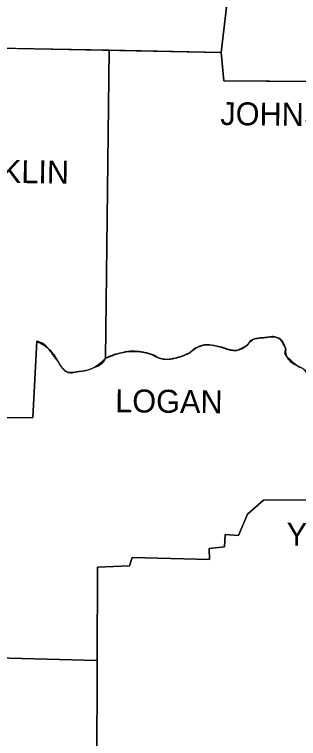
# Model space of a CAD drawing. Extents: x -28335 to 1228743, y -22428 to 152440.
# Drawn here: x 26423 to 27629, y 11936 to 15008 of the extents above; entities that cross this region are included whole.
import ezdxf

# ---------------------------------------------------------------- set-up
doc = ezdxf.new("R2010")
doc.units = 0
doc.layers.add('R_Draft', color=7, linetype='Continuous')
doc.layers.add('R_No Plot', color=7, linetype='Continuous')

msp = doc.modelspace()

# ---------------------------------------------------------------- linework, layer by layer
at = {"layer": 'R_Draft'}
for points in [[(24439, 16052.3), (24870.9, 16049.9), (24882.2, 16199.5), (25038.5, 16199.5), (25052.1, 16441.8), (25935.6, 16410.1), (25962.7, 16478.1), (26327.5, 16480.3), (26144, 15954.8), (26107.7, 15114.4), (26080.5, 15112.1), (26066.9, 14858.4), (26200.6, 14847.1), (26221, 14867.5), (27301.5, 14847.1), (27312.9, 14727)], [(27430.3, 16079.9), (27439.7, 15952.5), (27543.9, 15945.7), (27516.7, 15565.2), (27469.2, 15567.5), (27460.1, 15506.3), (27405.7, 15506.3), (27403.5, 15402.1), (27369.5, 15399.8), (27358.2, 15266.2), (27308.3, 15259.4), (27301.5, 15055.5), (27324.2, 15039.6), (27301.5, 14847.1)], [(27312.9, 14727), (29827.4, 14706.7), (29838.7, 14944.5), (30429, 14937.6)], [(26825.8, 14856.2), (26810, 13549.1)], [(26517.7, 13621.6), (26501.9, 13297.7), (26207.4, 13295.4), (26191.5, 13000.9), (25899.3, 13007.7), (25890.3, 12704.2), (25584.4, 12701.9), (25575.4, 12398.4), (25767.9, 12387), (25761.1, 12294.2), (26774.6, 12266.1)], [(28006, 13275), (27997, 12948.8), (27480.5, 12946.6), (27412.5, 12887.7), (27374, 12797.1), (27317.4, 12801.6), (27315.1, 12749.5), (27249.4, 12742.7), (27251.7, 12695.1), (26923.2, 12704.2), (26911.9, 12667.9), (26776, 12663.4), (26774.6, 12266.1)], [(26774.6, 12266.1), (26771.5, 11338.2), (26658.2, 11336), (26667.3, 11268), (26558.5, 11270.3), (26556.3, 11220.4), (26449.8, 11220.4), (26452.1, 11184.2), (26293.5, 11179.7), (26291.2, 11041.5), (26137.2, 11055.1), (26112.3, 9940.6), (25240.1, 9942.8), (25219.7, 9684.6), (25251.4, 9662), (25249.2, 9372), (24596, 9400.7)]]:
    msp.add_lwpolyline(points, dxfattribs=at)
for points in [[(26810, 13549.1), (26884.7, 13574), (26939.1, 13578.6), (26993.5, 13569.5), (27050.1, 13546.9), (27111.3, 13551.4), (27156.6, 13567.2), (27201.9, 13596.7), (27251.7, 13605.7), (27299.3, 13596.7), (27349.1, 13583.1), (27403.5, 13599), (27435.2, 13628.4), (27489.6, 13637.5), (27537.1, 13637.5), (27571.1, 13599), (27577.9, 13558.2), (27620.9, 13519.7), (27659.5, 13494.8), (27670.8, 13447.2), (27691.2, 13413.2), (27711.6, 13390.6), (27741, 13377), (27790.8, 13381.5), (27867.9, 13365.6), (27917.7, 13354.3), (27963, 13315.8), (28006, 13275)], [(26517.7, 13621.6), (26567.6, 13589.9), (26606.1, 13537.8), (26640.1, 13494.8), (26696.7, 13492.5), (26742, 13501.5), (26810, 13549.1)]]:
    msp.add_spline(points, degree=3, dxfattribs=at)
at = {"layer": 'R_No Plot'}
for p, q in [((26810, 13549.1), (26825.8, 14856.1)), ((26825.8, 14856.1), (26810, 13549.1)), ((26825.8, 14856.2), (26825.8, 14856.1)), ((26825.8, 14856.1), (27301.5, 14847.1)), ((27301.5, 14847.1), (26825.8, 14856.1)), ((27301.5, 14847.1), (27312.9, 14727)), ((27312.9, 14727), (27301.5, 14847.1)), ((27312.9, 14727), (28932.4, 14713.9)), ((28369.2, 14718.5), (27312.9, 14727)), ((27249.6, 13606), (27251.7, 13605.7)), ((27577.9, 13558.2), (27615.6, 13523.8)), ((27041.9, 13548.9), (27050.1, 13546.9)), ((27317.4, 12801.6), (27315.1, 12749.5)), ((27315.1, 12749.5), (27249.4, 12742.7)), ((26923.2, 12704.2), (26911.9, 12667.9)), ((26776, 12663.4), (26774.6, 12266.1)), ((26911.9, 12667.9), (26776, 12663.4)), ((26774.6, 12266.1), (26771.5, 11338.2))]:
    msp.add_line(p, q, dxfattribs=at)
for points in [[(26327.5, 16480.3), (26144, 15954.8), (26107.7, 15114.4), (26080.5, 15112.1), (26067.3, 14865.5), (26066.9, 14858.4), (26200.6, 14847.1), (26221, 14867.5), (26825.8, 14856.1)], [(27430.3, 16079.9), (27439.7, 15952.5), (27543.9, 15945.7), (27516.7, 15565.2), (27469.2, 15567.5), (27460.1, 15506.3), (27405.7, 15506.3), (27403.5, 15402.1), (27369.5, 15399.8), (27358.2, 15266.2), (27308.3, 15259.4), (27301.5, 15055.5), (27324.2, 15039.6), (27301.5, 14847.1)], [(27301.5, 14847.1), (27324.2, 15039.6), (27301.5, 15055.5), (27308.3, 15259.4)], [(26825.8, 14856.1), (26825.8, 14856.1), (26266.3, 14866.6)], [(26825.8, 14856.1), (26825.8, 14856.2)], [(25897.4, 12943.2), (25899.3, 13007.7), (26191.5, 13000.9), (26207.4, 13295.4), (26501.9, 13297.7), (26517.7, 13621.6)], [(26517.7, 13621.6), (26501.9, 13297.7), (26207.4, 13295.4)], [(26774.6, 12266.1), (26776, 12663.4), (26911.9, 12667.9), (26923.2, 12704.2), (27251.7, 12695.1), (27249.4, 12742.7), (27315.1, 12749.5), (27317.4, 12801.6), (27374, 12797.1), (27412.5, 12887.7), (27480.5, 12946.6), (27997, 12948.8), (28006, 13275)], [(28006, 13275), (27997, 12948.8), (27480.5, 12946.6), (27412.5, 12887.7)], [(25897.4, 12943.2), (25890.3, 12704.2), (25584.4, 12701.9), (25575.4, 12398.4), (25767.9, 12387), (25761.1, 12294.2), (26774.6, 12266.1)], [(27412.5, 12887.7), (27374, 12797.1), (27317.4, 12801.6)], [(27249.4, 12742.7), (27251.7, 12695.1), (26923.2, 12704.2)], [(26774.6, 12266.1), (25761.1, 12294.2), (25767.9, 12387), (25575.4, 12398.4), (25580.9, 12584.5)], [(26137.2, 11055.1), (26291.2, 11041.5), (26293.5, 11179.7), (26452.1, 11184.2), (26449.8, 11220.4), (26556.3, 11220.4), (26558.5, 11270.3), (26667.3, 11268), (26658.2, 11336), (26771.5, 11338.2), (26774.6, 12266.1)]]:
    msp.add_lwpolyline(points, dxfattribs=at)
for points, degree in [([(28006, 13275), (27992.2, 13289.2), (27977.5, 13302.3), (27963, 13315.8), (27948.5, 13329.3), (27936.6, 13347.1), (27917.7, 13354.3), (27901.5, 13360.5), (27884.5, 13362.1), (27867.9, 13365.6), (27842.2, 13371.1), (27816.5, 13376.5), (27790.8, 13381.5), (27774.5, 13384.7), (27757.5, 13374.4), (27741, 13377), (27730.3, 13378.6), (27720.4, 13383.2), (27711.6, 13390.6), (27703.2, 13397.5), (27697.2, 13404.8), (27691.2, 13413.2), (27683.3, 13424.1), (27676.8, 13435.5), (27670.8, 13447.2), (27663.3, 13461.6), (27670.7, 13482.3), (27659.5, 13494.8), (27648.9, 13506.5), (27633, 13510.3), (27620.9, 13519.7), (27605.7, 13531.5), (27590.5, 13543.2), (27577.9, 13558.2), (27568.9, 13568.9), (27577.7, 13586.3), (27571.1, 13599), (27562.9, 13614.6), (27554.1, 13632.2), (27537.1, 13637.5), (27521.4, 13642.3), (27505.3, 13639), (27489.6, 13637.5), (27471.3, 13635.7), (27453.1, 13634.2), (27435.2, 13628.4), (27421.2, 13623.9), (27417.3, 13606), (27403.5, 13599), (27385.4, 13589.8), (27367.3, 13579.8), (27349.1, 13583.1), (27332.5, 13586.1), (27316.1, 13592.9), (27299.3, 13596.7), (27283.5, 13600.2), (27267.6, 13603.7), (27251.7, 13605.7), (27235.1, 13607.8), (27218.4, 13603.6), (27201.9, 13596.7), (27184.2, 13589.3), (27173.1, 13574.8), (27156.6, 13567.2), (27141.9, 13560.5), (27126.9, 13555.3), (27111.3, 13551.4), (27091.3, 13546.3), (27069.8, 13543.3), (27050.1, 13546.9), (27030.5, 13550.4), (27013.4, 13564.7), (26993.5, 13569.5), (26975.5, 13573.9), (26957.3, 13577.7), (26939.1, 13578.6), (26921.1, 13579.4), (26902.7, 13578.1), (26884.7, 13574), (26858.7, 13568.1), (26834.1, 13560.4), (26810, 13549.1)], 3), ([(27419.3, 13614.7), (27423.8, 13620.6), (27428.2, 13626.1), (27435.2, 13628.4), (27453.1, 13634.2), (27471.3, 13635.7), (27489.6, 13637.5), (27505.3, 13639), (27521.4, 13642.3), (27537.1, 13637.5)], 3), ([(26567.6, 13589.9), (26555.2, 13605.6), (26536.1, 13615.8), (26517.7, 13621.6)], 2), ([(27341.6, 13584.7), (27344.1, 13584.1), (27346.6, 13583.6), (27349.1, 13583.1), (27367.3, 13579.8), (27385.4, 13589.8), (27403.5, 13599), (27410.4, 13602.5), (27414.8, 13608.8), (27419.3, 13614.7)], 3), ([(27537.1, 13637.5), (27554.1, 13632.2), (27562.9, 13614.6), (27571.1, 13599)], 2), ([(27156.6, 13567.2), (27173.1, 13574.8), (27184.2, 13589.3), (27201.9, 13596.7)], 2), ([(27201.9, 13596.7), (27217.7, 13603.3), (27233.7, 13607.5), (27249.6, 13606)], 2), ([(27251.7, 13605.7), (27267.6, 13603.7), (27283.5, 13600.2), (27299.3, 13596.7), (27313.6, 13593.5), (27327.5, 13588.1), (27341.6, 13584.7)], 3), ([(27571.1, 13599), (27577.7, 13586.3), (27568.9, 13568.9), (27577.9, 13558.2)], 2), ([(26810, 13549.1), (26797.8, 13524), (26768.9, 13511.3), (26742, 13501.5), (26727, 13496.1), (26711.9, 13494.3), (26696.7, 13492.5), (26678.1, 13490.3), (26655.9, 13481), (26640.1, 13494.8)], 3), ([(26810, 13549.1), (26834.1, 13560.4), (26858.7, 13568.1), (26884.7, 13574), (26902.7, 13578.1), (26921.1, 13579.4), (26939.1, 13578.6), (26957.3, 13577.7), (26975.5, 13573.9), (26993.5, 13569.5), (27000.4, 13567.8), (27007, 13565), (27013.5, 13561.8)], 3), ([(27013.5, 13561.8), (27023, 13557.2), (27032.2, 13552.1), (27041.9, 13548.9)], 2), ([(27060, 13545.6), (27076.9, 13544.4), (27094.6, 13547.2), (27111.3, 13551.4)], 2), ([(27111.3, 13551.4), (27126.9, 13555.3), (27141.9, 13560.5), (27156.6, 13567.2)], 2), ([(27050.1, 13546.9), (27053.4, 13546.3), (27056.7, 13545.9), (27060, 13545.6)], 2), ([(27615.6, 13523.8), (27617.4, 13522.5), (27619.2, 13521.1), (27620.9, 13519.7)], 2), ([(27620.9, 13519.7), (27625.5, 13516.1), (27630.7, 13513.3), (27635.9, 13510.7)], 2)]:
    msp.add_open_spline(points, degree=degree, dxfattribs=at)
for points in [[(26517.7, 13621.6), (26567.6, 13589.9), (26606.1, 13537.8), (26640.1, 13494.8), (26696.7, 13492.5), (26742, 13501.5), (26810, 13549.1)], [(26606.1, 13537.8), (26596.5, 13550.8), (26587, 13563.9), (26577.5, 13576.9), (26567.6, 13589.9)], [(26640.1, 13494.8), (26629.9, 13505), (26621.5, 13515.8), (26613.9, 13526.8), (26606.1, 13537.8)]]:
    msp.add_spline(points, degree=3, dxfattribs=at)

# ---------------------------------------------------------------- texts
at = {"layer": 'R_Draft'}
for s, rotation, p in [('JOHNSON', 359.3514, (27297, 14539)), ('FRANKLIN', 359.1816, (26010.3, 14298.9)), ('LOGAN', 359.3969, (26850.7, 13320.3)), ('YELL', 359.1987, (27577.9, 12754))]:
    msp.add_text(s, height=97.42, rotation=rotation, dxfattribs=at).set_placement(p)

doc.saveas('drawing.dxf')
